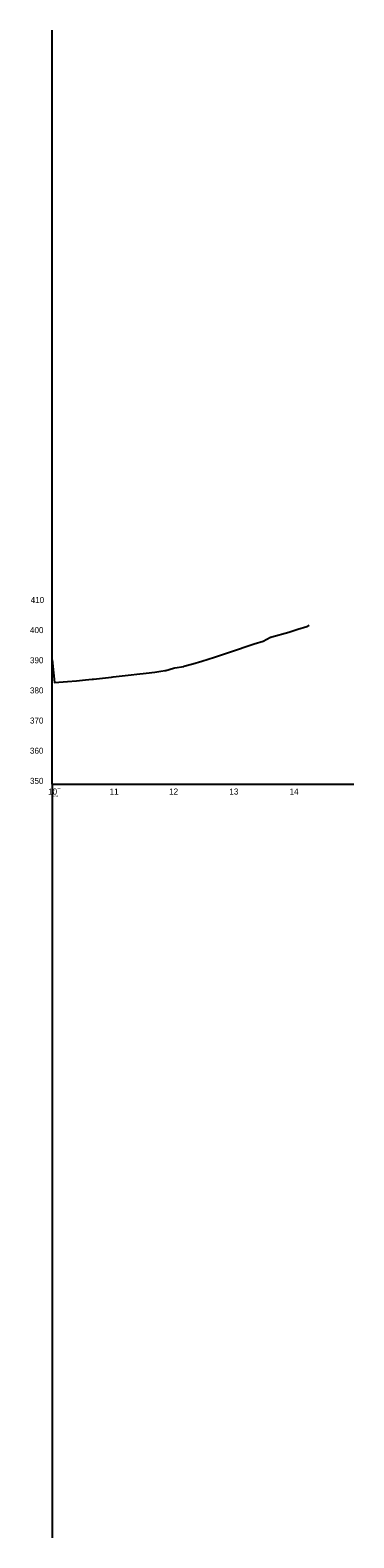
# Model space of a CAD drawing. Extents: x 99964 to 101300, y 93750 to 101250.
# Drawn here: x 99964 to 100500, y 93750 to 96250 of the extents above; entities that cross this region are included whole.
import ezdxf

# ---------------------------------------------------------------- set-up
doc = ezdxf.new("R2010")
doc.units = 0
for name, color, linetype in [('Exist Vertical Profile Ground Line', 7, 'Continuous'), ('Exist Vertical Profile Horizontal Axis Label Major', 7, 'Continuous'), ('Exist Vertical Profile Vertical Axis Label', 7, 'Continuous'), ('Old_Level_63', 7, 'Continuous')]:
    doc.layers.add(name, color=color, linetype=linetype)

msp = doc.modelspace()

# ---------------------------------------------------------------- linework, layer by layer
at = {"layer": 'Exist Vertical Profile Ground Line'}
msp.add_lwpolyline([(100000, 95205.7), (100003.8, 95168.1), (100011, 95168.7), (100025.7, 95170.1), (100040.7, 95171.2), (100055.6, 95172.6), (100066.5, 95173.8), (100068.5, 95174), (100083.4, 95175.6), (100098.4, 95177.3), (100101.2, 95177.6), (100116.3, 95179.3), (100131.2, 95181.1), (100140.3, 95182.1), (100140.6, 95182.1), (100155.7, 95183.9), (100170.3, 95185.4), (100180.5, 95186.9), (100187.3, 95188.2), (100188.4, 95188.4), (100201.3, 95191.9), (100203.2, 95192.4), (100218.3, 95195.1), (100218.4, 95195.2), (100233.3, 95199.1), (100248.4, 95203.7), (100258.6, 95207), (100268.9, 95210.5), (100283.8, 95215.4), (100298.9, 95220.4), (100309, 95223.8), (100319.8, 95227.3), (100334.6, 95232.2), (100349.7, 95237.1), (100362, 95243.3), (100362.6, 95243.5), (100364.1, 95244), (100392.1, 95251.7), (100407.1, 95256.8), (100422.1, 95261.2), (100426.1, 95263.4)], dxfattribs=at)
at = {"layer": 'Old_Level_63'}
for q in [(100000, 96250), (100500, 95000), (100000, 93750)]:
    msp.add_line((100000, 95000), q, dxfattribs=at)

# ---------------------------------------------------------------- texts
at = {"layer": 'Exist Vertical Profile Horizontal Axis Label Major'}
for s, p in [('10', (99993.6, 94982.5)), ('11', (100095.4, 94982.5)), ('12', (100194, 94982.5)), ('13', (100293.8, 94982.5)), ('14', (100393.6, 94982.5))]:
    msp.add_text(s, height=10, dxfattribs=at).set_placement(p)
at = {"layer": 'Exist Vertical Profile Vertical Axis Label'}
for s, p in [('410', (99964.6, 95300.2)), ('400', (99963.4, 95250.2)), ('390', (99963.4, 95200.2)), ('380', (99963.4, 95150.2)), ('370', (99963.4, 95100.2)), ('360', (99963.4, 95050.2)), ('350', (99963.4, 95000.2))]:
    msp.add_text(s, height=10, dxfattribs=at).set_placement(p)
at = {"layer": 'Old_Level_63'}
for s, p in [('RDY', (100000, 94998)), ('Y', (100000, 94994.8)), ('350', (100000, 94988.2)), ('50', (100000, 94985)), ('1000.000000', (100000, 94991.5)), ('10', (100000, 94981.8)), ('NOGAP', (100000, 94978.5))]:
    msp.add_text(s, height=2, dxfattribs=at).set_placement(p)

doc.saveas('drawing.dxf')
